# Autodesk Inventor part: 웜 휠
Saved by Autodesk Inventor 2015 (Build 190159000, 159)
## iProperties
Created: 2025-06
Part Number: 웜 휠
Material: 일반
Document SubType Name: Modeling
Designer: User
Density: 1 g/cm^3
Appearance: 기본값
Author: User
Author: jhkim
Creation Date: 2025-05-23
Sending System: Autodesk Inventor 2026
Preprocessor: ST-DEVELOPER v20.1
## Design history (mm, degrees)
node "웜 휠1"
body "Solid1"
node "기준1"
